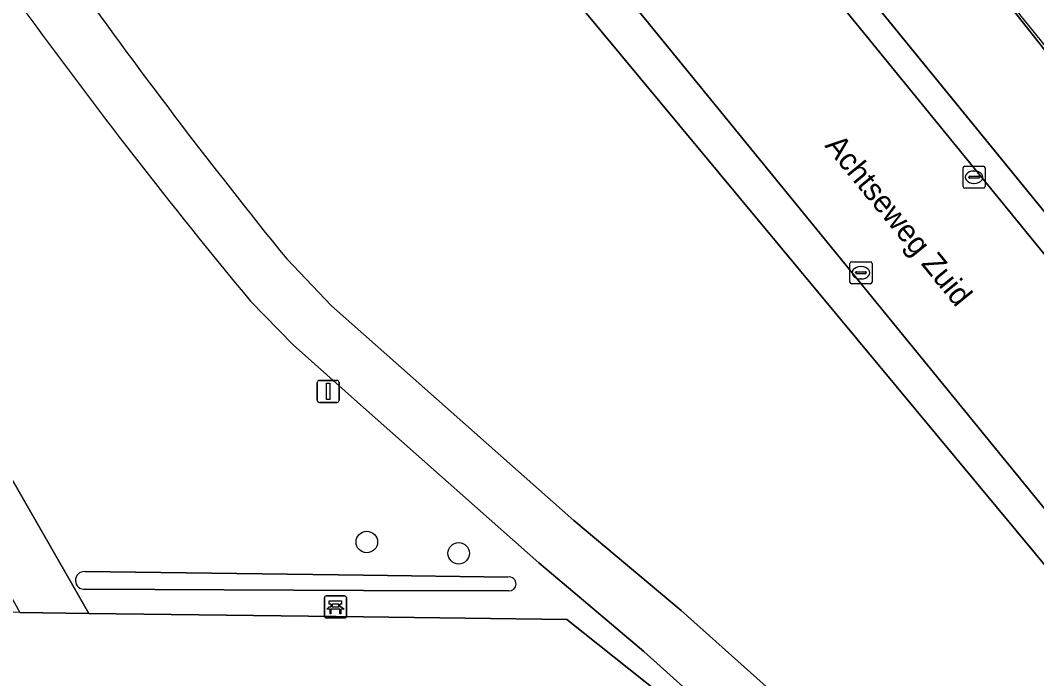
# Model space of a CAD drawing. Extents: x 157132 to 159279, y 384991 to 386650.
# Drawn here: x 158984.42 to 159030.56, y 385527.6 to 385557.48 of the extents above; entities that cross this region are included whole.
import ezdxf

# ---------------------------------------------------------------- set-up
doc = ezdxf.new("R2010")
doc.units = 0
for name, color, linetype in [('IMGEO_Bank', 7, 'Continuous'), ('IMGEO_Boom', 7, 'Continuous'), ('IMGEO_Fietspad_gesloten', 7, 'Continuous'), ('IMGEO_Gemengd_bos', 7, 'Continuous'), ('IMGEO_Grasland_overig', 7, 'Continuous'), ('IMGEO_Groenvoorziening', 7, 'Continuous'), ('IMGEO_Hek', 7, 'Continuous'), ('IMGEO_Kolk', 7, 'Continuous'), ('IMGEO_Lichtmast', 7, 'Continuous'), ('IMGEO_Muur', 7, 'Continuous'), ('IMGEO_Openbare_ruimte_label', 7, 'Continuous'), ('IMGEO_Rijbaan_lokaal_open', 7, 'Continuous'), ('IMGEO_Spoorbaan_halfverhard', 7, 'Continuous'), ('IMGEO_Voetpad_halfverhard', 7, 'Continuous'), ('IMGEO_Waterloop', 7, 'Continuous')]:
    doc.layers.add(name, color=color, linetype=linetype)

msp = doc.modelspace()

# ---------------------------------------------------------------- linework, layer by layer
at = {"layer": 'IMGEO_Bank'}
for p, q in [((158998.223, 385530.429), (158998.223, 385531.27)), ((158998.223, 385531.27), (158998.223, 385530.429)), ((158998.298, 385531.354), (158999.139, 385531.354)), ((158999.139, 385531.354), (158998.298, 385531.354)), ((158999.223, 385531.279), (158999.223, 385530.438)), ((158999.223, 385530.438), (158999.223, 385531.279)), ((158998.532, 385530.86), (158998.532, 385530.966)), ((158998.576, 385530.966), (158998.576, 385530.86)), ((158998.864, 385530.972), (158998.582, 385530.972)), ((158998.582, 385530.854), (158998.864, 385530.854)), ((158998.87, 385530.86), (158998.87, 385530.966)), ((158998.914, 385530.966), (158998.914, 385530.86)), ((158999.148, 385530.354), (158998.307, 385530.354)), ((158998.307, 385530.354), (158999.148, 385530.354)), ((158998.92, 385530.752), (158998.527, 385530.752))]:
    msp.add_line(p, q, dxfattribs=at)
for points in [[(158998.47, 385530.752), (158998.328, 385530.752), (158998.44, 385530.854), (158998.526, 385530.854)], [(158998.526, 385530.972), (158998.44, 385530.972), (158998.44, 385531.133), (158999.003, 385531.133), (158999.003, 385530.972), (158998.92, 385530.972)], [(158998.92, 385530.854), (158999.003, 385530.854), (158999.115, 385530.752), (158998.976, 385530.752)], [(158998.52, 385530.745), (158998.52, 385530.538), (158998.477, 385530.538), (158998.477, 385530.745)], [(158998.97, 385530.745), (158998.97, 385530.538), (158998.926, 385530.538), (158998.926, 385530.745)]]:
    msp.add_lwpolyline(points, dxfattribs=at)
for centre, radius, start, end in [((158998.301, 385531.276), 0.0779, 92.4484, 184.2845), ((158998.301, 385531.276), 0.0779, 92.4484, 184.2845), ((158999.145, 385531.276), 0.0779, 2.4484, 94.2845), ((158999.145, 385531.276), 0.0779, 2.4484, 94.2845), ((158998.525, 385530.965), 0.00671, 2.8957, 87.1043), ((158998.525, 385530.861), 0.00671, 272.8957, 357.1043), ((158998.582, 385530.965), 0.00671, 92.8957, 177.1043), ((158998.582, 385530.861), 0.00671, 182.8957, 267.1043), ((158998.864, 385530.965), 0.00671, 2.8957, 87.1043), ((158998.864, 385530.861), 0.00671, 272.8957, 357.1043), ((158998.921, 385530.965), 0.00671, 92.8957, 177.1043), ((158998.921, 385530.861), 0.00671, 182.8957, 267.1043), ((158998.301, 385530.432), 0.0779, 182.4484, 274.2845), ((158998.301, 385530.432), 0.0779, 182.4484, 274.2845), ((158998.47, 385530.745), 0.00671, 2.8957, 87.1043), ((158998.527, 385530.745), 0.00671, 92.8957, 177.1043), ((158998.919, 385530.745), 0.00671, 2.8957, 87.1043), ((158998.976, 385530.745), 0.00671, 92.8957, 177.1043), ((158999.145, 385530.432), 0.0779, 272.4484, 4.2845), ((158999.145, 385530.432), 0.0779, 272.4484, 4.2845)]:
    msp.add_arc(centre, radius, start, end, dxfattribs=at)
at = {"layer": 'IMGEO_Boom'}
for centre in [(159000.145, 385533.799), (159004.317, 385533.288)]:
    msp.add_circle(centre, 0.489, dxfattribs=at)
at = {"layer": 'IMGEO_Fietspad_gesloten'}
for points in [[(159029.142, 385517.709), (159024.86, 385521.359), (159014.416, 385530.685), (159009.545, 385534.784), (159000, 385543.24), (158998.547, 385544.527), (158996.509, 385546.653)], [(158994.864, 385544.734), (158996.799, 385542.746), (159000, 385539.908), (159007.959, 385532.852), (159009.112, 385531.88), (159012.731, 385528.828), (159016.755, 385525.22), (159023.033, 385519.591), (159027.421, 385515.87)]]:
    msp.add_lwpolyline(points, dxfattribs=at)
for centre, radius, start, end in [((159197.453, 385709.723), 258.786, 215.40958, 219.06009), ((159198.364, 385713.61), 264.445, 216.02464, 219.68787)]:
    msp.add_arc(centre, radius, start, end, dxfattribs=at)
at = {"layer": 'IMGEO_Gemengd_bos'}
for points in [[(159144.117, 385376.225), (159146.108, 385379.875), (159149.225, 385384.585), (159149.701, 385384.93), (159150.273, 385385.066), (159150.167, 385385.283), (159149.043, 385387.58), (159057.676, 385500), (159035.861, 385526.812), (159000, 385569.989), (158976.812, 385598.387), (158944.195, 385637.794), (158939.671, 385643.611), (158934.261, 385635.792)], [(158945.68, 385615.762), (158940.109, 385621.898), (158931.695, 385631.06), (158930.73, 385632.216), (158929.297, 385633.933), (158928.88, 385634.483), (158924.55, 385628.361), (158926.298, 385626.055), (158934.502, 385615.946), (158942.736, 385604.572), (158949.91, 385593.954), (158956.024, 385584.454), (158974.73, 385552.836), (158986.673, 385532.04), (158987.527, 385530.553), (159000, 385530.399), (159009.222, 385530.285), (159014.184, 385526.339), (159008.938, 385526.388), (159009.489, 385524.634), (159010.7, 385520.775), (159013.329, 385506.25), (159014.169, 385500), (159017.133, 385482.216)], [(158996.509, 385546.653), (158998.547, 385544.527), (159000, 385543.24), (159009.545, 385534.784), (159014.416, 385530.685), (159024.86, 385521.359), (159029.142, 385517.709)], [(159027.421, 385515.87), (159023.033, 385519.591), (159016.755, 385525.22), (159012.731, 385528.828), (159009.112, 385531.88), (159007.959, 385532.852), (159000, 385539.908), (158996.799, 385542.746), (158994.864, 385544.734)], [(158987.34, 385532.457), (159000, 385532.294), (159006.552, 385532.209)], [(159006.601, 385531.578), (159000, 385531.605), (158987.361, 385531.658)]]:
    msp.add_lwpolyline(points, dxfattribs=at)
for centre, radius, start, end in [((159197.453, 385709.723), 258.786, 215.40958, 219.06009), ((159198.364, 385713.61), 264.445, 216.02464, 219.68787), ((158987.319, 385532.057), 0.401, 87.0584, 181.7035), ((159006.606, 385531.896), 0.318, 357.1564, 99.8639), ((158987.32, 385532.057), 0.401, 181.7248, 275.8667), ((159006.605, 385531.898), 0.32, 269.3118, 356.8394)]:
    msp.add_arc(centre, radius, start, end, dxfattribs=at)
at = {"layer": 'IMGEO_Grasland_overig'}
msp.add_lwpolyline([(158956.024, 385584.454), (158949.91, 385593.954), (158942.736, 385604.572), (158934.502, 385615.946), (158926.298, 385626.055), (158924.55, 385628.361), (158923.552, 385626.951), (158925.024, 385624.93), (158934.45, 385612.148), (158946.132, 385595.065), (158954.63, 385582.053), (158962.047, 385570.297), (158971.411, 385553.928), (158983.478, 385532.213), (158984.386, 385530.602), (158987.527, 385530.553), (158986.673, 385532.04), (158974.73, 385552.836)], close=True, dxfattribs=at)
msp.add_lwpolyline([(159102.075, 385468.133), (159082.021, 385492.494), (159060.741, 385519), (159049.516, 385533.221), (159048.788, 385532.6), (159041.064, 385542.112), (159041.625, 385542.602), (159028.074, 385559.753), (159014.573, 385576.309), (159012.037, 385573.993), (159011.046, 385573.162), (159044.807, 385531.748), (159070.687, 385500), (159100.286, 385463.691)], dxfattribs=at)
at = {"layer": 'IMGEO_Groenvoorziening'}
msp.add_lwpolyline([(159167.2, 385381.706), (159100.286, 385463.691), (159070.687, 385500), (159044.807, 385531.748), (159011.046, 385573.162), (159010.937, 385573.296), (159000, 385586.793), (158885.494, 385728.344), (158857.155, 385763.115), (158856.922, 385762.926), (158855.151, 385763.341), (158855.067, 385763.287), (158854.563, 385763.33), (158854.381, 385763.213), (159043.862, 385530.978), (159167.844, 385378.971), (159168.01, 385379.124), (159168.092, 385379.623), (159168.34, 385381.585)], close=True, dxfattribs=at)
for points in [[(159151.54, 385384.447), (159151.995, 385383.713), (159152.806, 385382.628), (159153.706, 385384.827), (159038.204, 385526.376), (158938.905, 385648.068), (158937.569, 385646.098), (158938.459, 385644.928)], [(158939.803, 385643.802), (158939.671, 385643.611), (158944.195, 385637.794), (158976.812, 385598.387), (159000, 385569.989), (159035.861, 385526.812), (159057.676, 385500), (159149.043, 385387.58), (159150.167, 385385.283), (159150.273, 385385.066)]]:
    msp.add_lwpolyline(points, dxfattribs=at)
at = {"layer": 'IMGEO_Hek'}
msp.add_lwpolyline([(159096.003, 385475.701), (159072.576, 385504.374), (159069.092, 385508.611), (159058.304, 385522.356), (159049.446, 385533.456), (159048.76, 385532.887), (159041.105, 385542.147), (159041.869, 385542.754), (159037.056, 385548.748), (159030.78, 385556.527), (159022.964, 385566.189), (159018.242, 385572.067), (159014.652, 385576.334), (159010.945, 385573.278), (159004.672, 385581.054), (158979.577, 385611.994), (158960.792, 385635.337)], dxfattribs=at)
at = {"layer": 'IMGEO_Kolk'}
for p, q in [((159027.217, 385549.933), (159027.217, 385550.785)), ((159027.292, 385550.859), (159028.144, 385550.859)), ((159027.705, 385550.639), (159027.73, 385550.639)), ((159028.218, 385550.785), (159028.218, 385549.933)), ((159027.476, 385550.353), (159027.476, 385550.365)), ((159027.914, 385550.316), (159027.516, 385550.316)), ((159027.519, 385550.402), (159027.917, 385550.402)), ((159027.96, 385550.365), (159027.96, 385550.353)), ((159028.144, 385549.859), (159027.292, 385549.859)), ((159027.728, 385550.079), (159027.703, 385550.079)), ((159022.157, 385546.523), (159023.009, 385546.523)), ((159022.082, 385545.597), (159022.082, 385546.449)), ((159022.341, 385546.017), (159022.341, 385546.029)), ((159022.384, 385546.066), (159022.782, 385546.066)), ((159022.57, 385546.303), (159022.595, 385546.303)), ((159022.825, 385546.029), (159022.825, 385546.017)), ((159023.083, 385546.449), (159023.083, 385545.597)), ((159022.779, 385545.98), (159022.381, 385545.98)), ((159022.593, 385545.743), (159022.568, 385545.743)), ((159023.009, 385545.523), (159022.157, 385545.523))]:
    msp.add_line(p, q, dxfattribs=at)
for points in [[(159027.217, 385549.933), (159027.217, 385550.785)], [(159027.292, 385550.859), (159028.144, 385550.859)], [(159028.218, 385550.785), (159028.218, 385549.933)], [(159028.144, 385549.859), (159027.292, 385549.859)], [(159022.157, 385546.523), (159023.009, 385546.523)], [(159022.082, 385545.597), (159022.082, 385546.449)], [(159023.083, 385546.449), (159023.083, 385545.597)], [(159023.009, 385545.523), (159022.157, 385545.523)]]:
    msp.add_lwpolyline(points, dxfattribs=at)
for centre, radius, start, end in [((159027.294, 385550.783), 0.0765, 91.552, 178.448), ((159027.294, 385550.783), 0.0765, 91.552, 178.448), ((159028.142, 385550.783), 0.0765, 1.552, 88.448), ((159028.142, 385550.783), 0.0765, 1.552, 88.448), ((159027.516, 385550.362), 0.0403, 85.8775, 175.7526), ((159027.513, 385550.352), 0.0366, 178.938, 274.7102), ((159027.917, 385550.359), 0.043, 264.8664, 352.4533), ((159027.921, 385550.364), 0.0386, 1.7309, 96.639), ((159027.294, 385549.935), 0.0765, 181.552, 268.448), ((159027.294, 385549.935), 0.0765, 181.552, 268.448), ((159028.142, 385549.935), 0.0765, 271.552, 358.448), ((159028.142, 385549.935), 0.0765, 271.552, 358.448), ((159022.159, 385546.447), 0.0765, 91.552, 178.448), ((159022.159, 385546.447), 0.0765, 91.552, 178.448), ((159023.007, 385546.447), 0.0765, 1.552, 88.448), ((159023.007, 385546.447), 0.0765, 1.552, 88.448), ((159022.381, 385546.026), 0.0403, 85.8775, 175.7526), ((159022.378, 385546.016), 0.0366, 178.938, 274.7102), ((159022.782, 385546.023), 0.043, 264.8664, 352.4533), ((159022.786, 385546.028), 0.0386, 1.7309, 96.639), ((159022.159, 385545.599), 0.0765, 181.552, 268.448), ((159022.159, 385545.599), 0.0765, 181.552, 268.448), ((159023.007, 385545.599), 0.0765, 271.552, 358.448), ((159023.007, 385545.599), 0.0765, 271.552, 358.448)]:
    msp.add_arc(centre, radius, start, end, dxfattribs=at)
for centre, major_axis, ratio, start_param, end_param in [((159027.704, 385550.359), (-0.387, 0.002), 0.722429, 4.712389, 7.853982), ((159027.729, 385550.359), (-0.39, 0.002), 0.717154, 1.570796, 4.712389), ((159022.569, 385546.023), (-0.387, 0.002), 0.722429, 4.712389, 7.853982), ((159022.594, 385546.023), (-0.39, 0.002), 0.717154, 1.570796, 4.712389)]:
    msp.add_ellipse(centre, major_axis=major_axis, ratio=ratio, start_param=start_param, end_param=end_param, dxfattribs=at)
at = {"layer": 'IMGEO_Lichtmast'}
for p, q in [((158997.895, 385540.238), (158997.895, 385541.038)), ((158997.895, 385541.038), (158997.895, 385540.238)), ((158997.995, 385541.138), (158998.785, 385541.138)), ((158998.785, 385541.138), (158997.995, 385541.138)), ((158998.885, 385541.038), (158998.885, 385540.238)), ((158998.885, 385540.238), (158998.885, 385541.038)), ((158998.785, 385540.138), (158997.995, 385540.138)), ((158997.995, 385540.138), (158998.785, 385540.138))]:
    msp.add_line(p, q, dxfattribs=at)
msp.add_lwpolyline([(158998.315, 385541.013), (158998.465, 385541.013), (158998.465, 385540.263), (158998.315, 385540.263), (158998.315, 385541.013)], dxfattribs=at)
for centre, start, end in [((158997.995, 385541.038), 90, 180), ((158997.995, 385541.038), 90, 180), ((158998.785, 385541.038), 0, 90), ((158998.785, 385541.038), 360, 90), ((158997.995, 385540.238), 180, 270), ((158997.995, 385540.238), 180, 270), ((158998.785, 385540.238), 270, 0), ((158998.785, 385540.238), 270, 0)]:
    msp.add_arc(centre, 0.1, start, end, dxfattribs=at)
at = {"layer": 'IMGEO_Muur'}
msp.add_lwpolyline([(159010.937, 385573.296), (159044.807, 385531.748), (159100.286, 385463.691), (159167.2, 385381.706), (159168.34, 385381.585), (159168.595, 385381.558), (159169.474, 385380.494), (159169.729, 385380.185), (159170.502, 385379.248), (159170.444, 385378.688), (159170.356, 385377.836), (159224.612, 385309.725), (159249.549, 385278.463)], dxfattribs=at)
at = {"layer": 'IMGEO_Rijbaan_lokaal_open'}
msp.add_lwpolyline([(159043.862, 385530.978), (158854.381, 385763.213), (158848.245, 385759.247), (158935.542, 385652.189), (158938.905, 385648.068), (159038.204, 385526.376), (159153.706, 385384.827), (159161.083, 385375.787), (159162.514, 385374.032), (159167.844, 385378.971)], close=True, dxfattribs=at)
at = {"layer": 'IMGEO_Spoorbaan_halfverhard'}
msp.add_lwpolyline([(158959.648, 385644.849), (158984.94, 385614.139), (159014.573, 385576.309), (159028.074, 385559.753), (159041.625, 385542.602), (159042.082, 385542.991), (159049.811, 385533.48), (159049.516, 385533.221), (159060.741, 385519), (159082.021, 385492.494), (159102.075, 385468.133), (159114.976, 385452.124), (159124.294, 385441.044), (159146.986, 385413.255), (159168.76, 385387.107), (159181.227, 385371.527), (159195.791, 385354.347), (159205.058, 385342.95), (159218.546, 385326.665)], dxfattribs=at)
at = {"layer": 'IMGEO_Voetpad_halfverhard'}
for points in [[(159009.222, 385530.285), (159000, 385530.399), (158987.527, 385530.553), (158984.386, 385530.602), (158970.301, 385530.822), (158962.196, 385530.769)], [(158965.155, 385526.82), (158986.361, 385526.609), (158987.993, 385526.593), (159000, 385526.475), (159005.896, 385526.417), (159008.938, 385526.388), (159014.184, 385526.339), (159009.222, 385530.285)]]:
    msp.add_lwpolyline(points, dxfattribs=at)
at = {"layer": 'IMGEO_Waterloop'}
for points in [[(159006.552, 385532.209), (159000, 385532.294), (158987.34, 385532.457)], [(158987.361, 385531.658), (159000, 385531.605), (159006.601, 385531.578)]]:
    msp.add_lwpolyline(points, dxfattribs=at)
for centre, radius, start, end in [((158987.319, 385532.057), 0.401, 87.0584, 181.7035), ((159006.606, 385531.896), 0.318, 357.1564, 99.8639), ((158987.32, 385532.057), 0.401, 181.7248, 275.8667), ((159006.605, 385531.898), 0.32, 269.3118, 356.8394)]:
    msp.add_arc(centre, radius, start, end, dxfattribs=at)

# ---------------------------------------------------------------- texts
at = {"layer": 'IMGEO_Openbare_ruimte_label'}
msp.add_text('Achtseweg Zuid', height=1, rotation=309.2411, dxfattribs=at).set_placement((159020.908, 385551.78))

doc.saveas('drawing.dxf')
